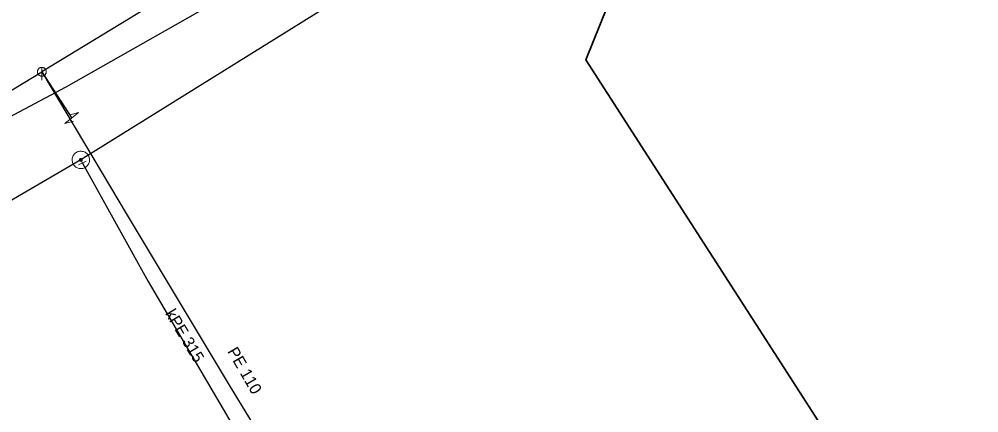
# Model space of a CAD drawing. Extents: x -687468 to -685917, y -974192 to -973456.
# Drawn here: x -686202 to -686146.9, y -973594.5 to -973571.9 of the extents above; entities that cross this region are included whole.
import ezdxf
from ezdxf.enums import TextEntityAlignment as Align

# ---------------------------------------------------------------- set-up
doc = ezdxf.new("R2010")
doc.units = 0
doc.header["$LTSCALE"] = 0.27
for name, color, linetype, lineweight in [('1', 7, 'Continuous', 13), ('14', 7, 'Continuous', 25), ('17', 7, 'Continuous', 25), ('22', 7, 'Continuous', 13), ('31', 7, 'Continuous', 13), ('34', 7, 'Continuous', 13), ('47', 7, 'Continuous', 13)]:
    doc.layers.add(name, color=color, linetype=linetype, lineweight=lineweight)

msp = doc.modelspace()

# ---------------------------------------------------------------- linework, layer by layer
at = {"layer": '14'}
msp.add_line((-686164.87, -973553.19), (-686200.73, -973574.96), dxfattribs=at)
at = {"layer": '14', "lineweight": 13}
msp.add_line((-686198.489, -973580.019), (-686198.399, -973580.199), dxfattribs=at)
at = {"layer": '14'}
for points in [[(-686235.469, -973596), (-686234.388, -973595.344), (-686219.48, -973586.316), (-686219.052, -973586.057), (-686200.73, -973574.96), (-686199.012, -973577.618)], [(-686200.73, -973574.96), (-686195.82, -973583.199), (-686189.969, -973592.96), (-686186.46, -973598.699), (-686180.69, -973608.329)]]:
    msp.add_lwpolyline(points, dxfattribs=at)
at = {"layer": '17'}
msp.add_line((-686198.489, -973580.019), (-686215.348, -973589.807), dxfattribs=at)
for points in [[(-686148.68, -973547.12), (-686199.359, -973575.84), (-686213.05, -973583.12), (-686218.669, -973575.249)], [(-686149.557, -973550.584), (-686155.469, -973554.27), (-686181.98, -973569.739), (-686198.489, -973580.019)], [(-686198.399, -973580.199), (-686194.62, -973587), (-686189.789, -973595.21), (-686185.35, -973602.78), (-686179.62, -973611.64), (-686175.8, -973619.199), (-686173.53, -973624.27), (-686171.69, -973630.71), (-686170.809, -973636.51)]]:
    msp.add_lwpolyline(points, dxfattribs=at)
at = {"layer": '17', "lineweight": 35}
msp.add_lwpolyline([(-686160.425, -973551.891), (-686169.469, -973574.282), (-686122.999, -973646.384), (-686098.932, -973712.353), (-686089.329, -973782.048), (-686297.791, -974027.806), (-686326.807, -974076.614), (-686379.703, -974100.561), (-686411.584, -974111.413)], dxfattribs=at)
at = {"layer": '22'}
msp.add_line((-686200.729, -973574.708), (-686200.73, -973575.451), dxfattribs=at)
msp.add_lwpolyline([(-686200.478, -973574.96), (-686200.479, -973574.934), (-686200.483, -973574.908), (-686200.489, -973574.882), (-686200.499, -973574.858), (-686200.511, -973574.834), (-686200.525, -973574.812), (-686200.542, -973574.791), (-686200.56, -973574.773), (-686200.581, -973574.756), (-686200.603, -973574.742), (-686200.627, -973574.73), (-686200.651, -973574.72), (-686200.677, -973574.714), (-686200.703, -973574.71), (-686200.729, -973574.708), (-686200.755, -973574.709), (-686200.781, -973574.713), (-686200.807, -973574.719), (-686200.832, -973574.729), (-686200.855, -973574.741), (-686200.877, -973574.755), (-686200.898, -973574.772), (-686200.916, -973574.79), (-686200.933, -973574.811), (-686200.947, -973574.833), (-686200.959, -973574.857), (-686200.969, -973574.881), (-686200.976, -973574.907), (-686200.98, -973574.933), (-686200.982, -973574.959), (-686200.981, -973574.985), (-686200.977, -973575.011), (-686200.97, -973575.037), (-686200.96, -973575.062), (-686200.948, -973575.085), (-686200.934, -973575.107), (-686200.917, -973575.128), (-686200.899, -973575.146), (-686200.878, -973575.163), (-686200.856, -973575.177), (-686200.833, -973575.189), (-686200.808, -973575.199), (-686200.782, -973575.206), (-686200.756, -973575.21), (-686200.73, -973575.212), (-686200.704, -973575.211), (-686200.678, -973575.207), (-686200.652, -973575.2), (-686200.628, -973575.19), (-686200.604, -973575.178), (-686200.582, -973575.164), (-686200.561, -973575.147), (-686200.543, -973575.129), (-686200.526, -973575.108), (-686200.512, -973575.086), (-686200.5, -973575.063), (-686200.49, -973575.038), (-686200.484, -973575.012), (-686200.48, -973574.986)], close=True, dxfattribs=at)
at = {"layer": '31'}
msp.add_line((-686198.616, -973577.297), (-686199.106, -973577.44), dxfattribs=at)
msp.add_lwpolyline([(-686198.616, -973577.297), (-686199.407, -973577.938), (-686198.917, -973577.795)], dxfattribs=at)
at = {"layer": '34'}
msp.add_line((-686198.621, -973580.308), (-686198.176, -973580.089), dxfattribs=at)
at = {"layer": '47'}
for points in [[(-686198.06, -973579.761), (-686198.089, -973579.718), (-686198.123, -973579.678), (-686198.16, -973579.642), (-686198.201, -973579.609), (-686198.246, -973579.581), (-686198.293, -973579.559), (-686198.342, -973579.541), (-686198.393, -973579.529), (-686198.444, -973579.521), (-686198.497, -973579.519), (-686198.549, -973579.522), (-686198.601, -973579.532), (-686198.651, -973579.546), (-686198.7, -973579.566), (-686198.746, -973579.59), (-686198.789, -973579.619), (-686198.829, -973579.653), (-686198.866, -973579.691), (-686198.898, -973579.731), (-686198.926, -973579.776), (-686198.948, -973579.823), (-686198.967, -973579.873), (-686198.979, -973579.923), (-686198.987, -973579.975), (-686198.988, -973580.027), (-686198.985, -973580.079), (-686198.976, -973580.131), (-686198.961, -973580.181), (-686198.941, -973580.23), (-686198.917, -973580.276), (-686198.888, -973580.319), (-686198.854, -973580.359), (-686198.817, -973580.396), (-686198.776, -973580.428), (-686198.731, -973580.456), (-686198.685, -973580.479), (-686198.635, -973580.497), (-686198.584, -973580.51), (-686198.532, -973580.517), (-686198.48, -973580.518), (-686198.428, -973580.515), (-686198.377, -973580.506), (-686198.326, -973580.491), (-686198.277, -973580.471), (-686198.231, -973580.447), (-686198.188, -973580.418), (-686198.148, -973580.384), (-686198.112, -973580.347), (-686198.079, -973580.306), (-686198.051, -973580.261), (-686198.028, -973580.215), (-686198.011, -973580.166), (-686197.998, -973580.115), (-686197.991, -973580.063), (-686197.989, -973580.01), (-686197.992, -973579.958), (-686198.001, -973579.907), (-686198.016, -973579.856), (-686198.036, -973579.807)], [(-686198.418, -973579.976), (-686198.423, -973579.969), (-686198.429, -973579.963), (-686198.434, -973579.957), (-686198.441, -973579.952), (-686198.449, -973579.947), (-686198.457, -973579.943), (-686198.464, -973579.94), (-686198.473, -973579.938), (-686198.481, -973579.937), (-686198.49, -973579.937), (-686198.499, -973579.937), (-686198.507, -973579.939), (-686198.515, -973579.941), (-686198.523, -973579.944), (-686198.531, -973579.948), (-686198.538, -973579.953), (-686198.544, -973579.959), (-686198.55, -973579.964), (-686198.555, -973579.971), (-686198.56, -973579.979), (-686198.564, -973579.987), (-686198.567, -973579.994), (-686198.569, -973580.003), (-686198.571, -973580.012), (-686198.57, -973580.02), (-686198.57, -973580.029), (-686198.568, -973580.037), (-686198.566, -973580.045), (-686198.563, -973580.053), (-686198.559, -973580.061), (-686198.554, -973580.068), (-686198.548, -973580.074), (-686198.543, -973580.08), (-686198.536, -973580.085), (-686198.528, -973580.09), (-686198.521, -973580.094), (-686198.513, -973580.097), (-686198.504, -973580.099), (-686198.495, -973580.101), (-686198.487, -973580.1), (-686198.478, -973580.1), (-686198.47, -973580.098), (-686198.462, -973580.096), (-686198.454, -973580.093), (-686198.446, -973580.089), (-686198.439, -973580.084), (-686198.433, -973580.078), (-686198.427, -973580.073), (-686198.422, -973580.066), (-686198.417, -973580.058), (-686198.413, -973580.051), (-686198.41, -973580.043), (-686198.408, -973580.034), (-686198.407, -973580.026), (-686198.407, -973580.017), (-686198.407, -973580.008), (-686198.409, -973580), (-686198.411, -973579.992), (-686198.414, -973579.984)]]:
    msp.add_lwpolyline(points, close=True, dxfattribs=at)

# ---------------------------------------------------------------- texts
at = {"layer": '1'}
for s, rotation, p in [('kPE 315 ', 301, (-686192.733, -973590.383)), ('PE 110', 300, (-686189.355, -973592.276))]:
    msp.add_text(s, height=0.6667, rotation=rotation, dxfattribs=at).set_placement(p, align=Align.CENTER)

doc.saveas('drawing.dxf')
